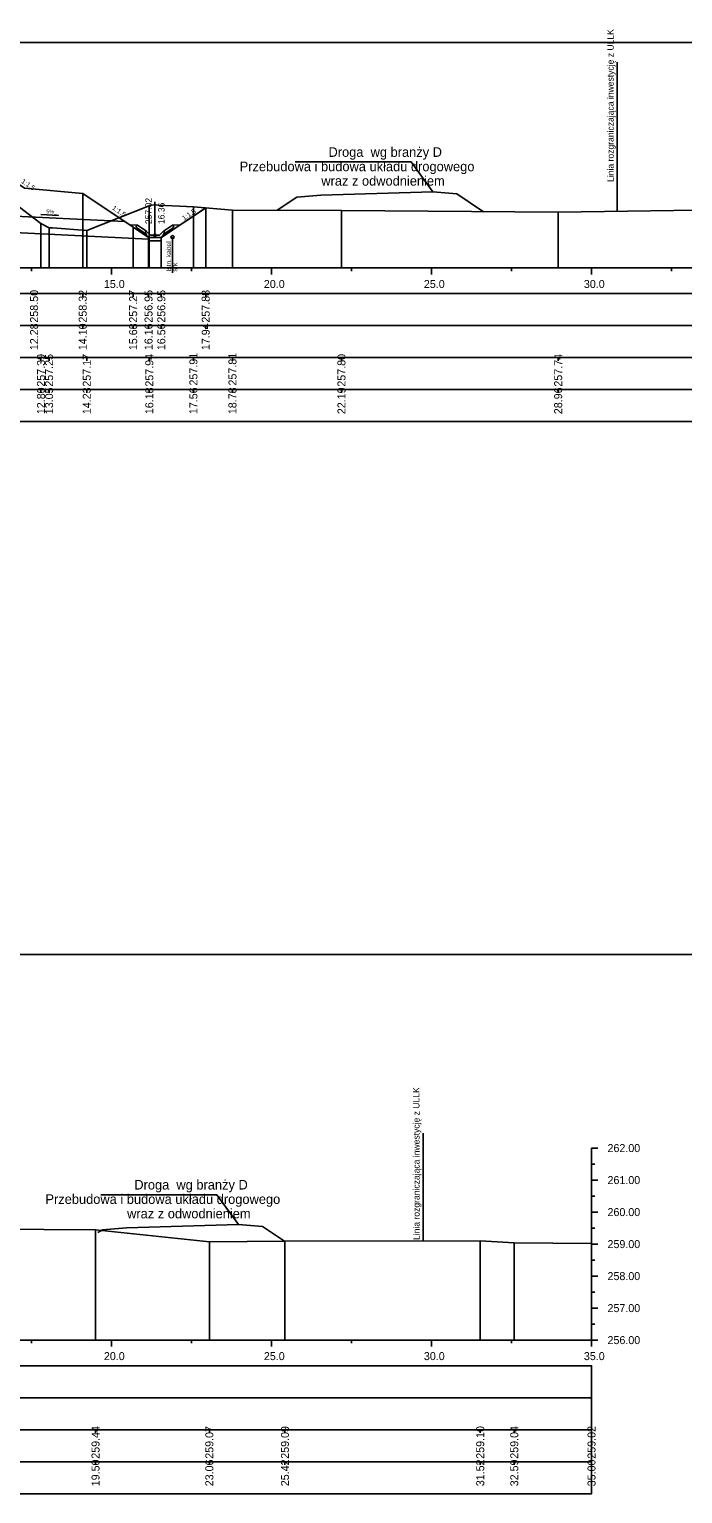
# Model space of a CAD drawing. Extents: x 6516023 to 6560129, y 5513077 to 5529206.
# Drawn here: x 6516497.89 to 6516518.31, y 5514501.31 to 5514547.06 of the extents above; entities that cross this region are included whole.
import ezdxf

# ---------------------------------------------------------------- set-up
doc = ezdxf.new("R2010")
doc.units = 0
for name, color, linetype in [('IR_default', 7, 'Continuous'), ('TOR_PRZEK_P-inne branze', 7, 'Continuous'), ('TOR_PRZEK_P-kable', 7, 'Continuous'), ('TOR_PRZEK_P-odwodnienie', 7, 'Continuous'), ('TOR_PRZEK_P-opisy', 7, 'Continuous'), ('TOR_PRZEK_P-schodkowanie+wymiana', 7, 'Continuous'), ('TOR_PRZEK_P-tabelka istniejace', 7, 'Continuous'), ('TOR_PRZEK_P-tabelka projektowane', 7, 'Continuous'), ('TOR_PRZEK_P-teren istniejacy', 7, 'Continuous'), ('TOR_PRZEK_P-uklad odniesienia', 7, 'Continuous'), ('TOR_PRZEK_P-warstwa ochronna II', 7, 'Continuous'), ('TOR_PS_T-granica PKP-projektowana', 7, 'Continuous'), ('TOR_PS_T-skarpy projektowane', 7, 'Continuous'), ('TOR_RAMKI-ramka+tabelka 1', 7, 'Continuous')]:
    doc.layers.add(name, color=color, linetype=linetype)

msp = doc.modelspace()

# ---------------------------------------------------------------- linework, layer by layer
at = {"layer": 'IR_default'}
msp.add_lwpolyline([(6516497.745, 5514542.101), (6516499.564, 5514541.929), (6516501.138, 5514540.88), (6516501.14, 5514540.878), (6516501.62, 5514540.559), (6516501.62, 5514540.558), (6516502.02, 5514540.558), (6516502.02, 5514540.558), (6516502.769, 5514541.057), (6516502.77, 5514541.058), (6516503.406, 5514541.483)], dxfattribs=at)
at = {"layer": 'TOR_PRZEK_P-inne branze'}
for p, q in [((6516509.824, 5514542.919), (6516506.2, 5514542.919)), ((6516510.5, 5514541.985), (6516509.824, 5514542.919)), ((6516503.755, 5514510.65), (6516500.131, 5514510.65)), ((6516504.431, 5514509.716), (6516503.755, 5514510.65))]:
    msp.add_line(p, q, dxfattribs=at)
for points in [[(6516505.636, 5514541.41), (6516506.25, 5514541.819), (6516507, 5514541.879), (6516508.75, 5514541.932), (6516510.5, 5514541.985), (6516511.25, 5514541.925), (6516512.09, 5514541.365)], [(6516500.04, 5514509.47), (6516500.181, 5514509.551), (6516500.931, 5514509.611), (6516502.681, 5514509.664), (6516504.431, 5514509.716), (6516505.181, 5514509.656), (6516505.873, 5514509.195)]]:
    msp.add_lwpolyline(points, dxfattribs=at)
at = {"layer": 'TOR_PRZEK_P-kable'}
msp.add_line((6516502.369, 5514540.568), (6516502.369, 5514539.458), dxfattribs=at)
msp.add_circle((6516502.369, 5514540.568), 0.05, dxfattribs=at)
at = {"layer": 'TOR_PRZEK_P-odwodnienie'}
for p, q in [((6516501.819, 5514540.628), (6516501.819, 5514541.672)), ((6516501.554, 5514540.754), (6516501.274, 5514540.941)), ((6516502.084, 5514540.754), (6516502.364, 5514540.941)), ((6516501.51, 5514540.687), (6516501.249, 5514540.861)), ((6516501.521, 5514540.704), (6516501.51, 5514540.687)), ((6516501.512, 5514540.723), (6516501.559, 5514540.747)), ((6516501.554, 5514540.754), (6516501.546, 5514540.741)), ((6516501.679, 5514540.628), (6516501.559, 5514540.747)), ((6516501.629, 5514540.558), (6516502.009, 5514540.558)), ((6516501.679, 5514540.628), (6516501.959, 5514540.628)), ((6516501.959, 5514540.628), (6516502.079, 5514540.747)), ((6516502.079, 5514540.747), (6516502.127, 5514540.723)), ((6516502.084, 5514540.754), (6516502.092, 5514540.741)), ((6516502.117, 5514540.704), (6516502.128, 5514540.687)), ((6516502.128, 5514540.687), (6516502.389, 5514540.861))]:
    msp.add_line(p, q, dxfattribs=at)
for points in [[(6516501.028, 5514540.952), (6516501.274, 5514540.941)], [(6516501.224, 5514540.914), (6516501.274, 5514540.941)], [(6516501.224, 5514540.914), (6516501.249, 5514540.861)], [(6516502.611, 5514540.952), (6516502.364, 5514540.941)], [(6516502.414, 5514540.914), (6516502.364, 5514540.941)], [(6516502.414, 5514540.914), (6516502.389, 5514540.861)], [(6516501.546, 5514540.741), (6516501.511, 5514540.723)], [(6516501.511, 5514540.723), (6516501.521, 5514540.704)], [(6516501.559, 5514540.628), (6516501.512, 5514540.723)], [(6516501.629, 5514540.558), (6516501.559, 5514540.628)], [(6516501.619, 5514540.558), (6516501.619, 5514540.559), (6516501.619, 5514540.558), (6516501.619, 5514540.558), (6516501.619, 5514540.558), (6516501.62, 5514540.558), (6516501.619, 5514540.558), (6516501.62, 5514540.559)], [(6516502.019, 5514540.558), (6516501.619, 5514540.558), (6516501.619, 5514540.458), (6516502.019, 5514540.458), (6516502.019, 5514540.558)], [(6516502.009, 5514540.558), (6516502.079, 5514540.628)], [(6516502.019, 5514540.558), (6516502.019, 5514540.559), (6516502.019, 5514540.558), (6516502.019, 5514540.558), (6516502.019, 5514540.558), (6516502.02, 5514540.558), (6516502.019, 5514540.558), (6516502.02, 5514540.559)], [(6516502.079, 5514540.628), (6516502.127, 5514540.723)], [(6516502.092, 5514540.741), (6516502.127, 5514540.723)], [(6516502.127, 5514540.723), (6516502.117, 5514540.704)]]:
    msp.add_lwpolyline(points, dxfattribs=at)
msp.add_circle((6516501.819, 5514540.628), 0.035, dxfattribs=at)
at = {"layer": 'TOR_PRZEK_P-schodkowanie+wymiana'}
for p, q in [((6516497.011, 5514541.248), (6516500.874, 5514541.055)), ((6516497.011, 5514540.733), (6516501.619, 5514540.503))]:
    msp.add_line(p, q, dxfattribs=at)
at = {"layer": 'TOR_PRZEK_P-tabelka istniejace'}
for p, q in [((6516498.259, 5514536.706), (6516498.259, 5514536.806)), ((6516498.511, 5514536.706), (6516498.511, 5514536.806)), ((6516499.689, 5514536.706), (6516499.689, 5514536.806)), ((6516501.644, 5514536.706), (6516501.644, 5514536.806)), ((6516503.022, 5514536.706), (6516503.022, 5514536.806)), ((6516504.243, 5514536.706), (6516504.243, 5514536.806)), ((6516507.649, 5514536.706), (6516507.649, 5514536.806)), ((6516514.421, 5514536.706), (6516514.421, 5514536.806)), ((6516446.663, 5514535.806), (6516520.463, 5514535.806)), ((6516498.259, 5514535.706), (6516498.259, 5514535.806)), ((6516498.511, 5514535.706), (6516498.511, 5514535.806)), ((6516499.689, 5514535.706), (6516499.689, 5514535.806)), ((6516501.644, 5514535.706), (6516501.644, 5514535.806)), ((6516503.022, 5514535.706), (6516503.022, 5514535.806)), ((6516504.243, 5514535.706), (6516504.243, 5514535.806)), ((6516507.649, 5514535.706), (6516507.649, 5514535.806)), ((6516514.421, 5514535.706), (6516514.421, 5514535.806)), ((6516499.963, 5514503.206), (6516499.963, 5514503.306)), ((6516503.52, 5514503.206), (6516503.52, 5514503.306)), ((6516505.884, 5514503.206), (6516505.884, 5514503.306)), ((6516511.985, 5514503.206), (6516511.985, 5514503.306)), ((6516513.049, 5514503.206), (6516513.049, 5514503.306)), ((6516515.463, 5514503.206), (6516515.463, 5514503.306)), ((6516441.663, 5514502.306), (6516515.463, 5514502.306)), ((6516499.963, 5514502.206), (6516499.963, 5514502.306)), ((6516503.52, 5514502.206), (6516503.52, 5514502.306)), ((6516505.884, 5514502.206), (6516505.884, 5514502.306)), ((6516511.985, 5514502.206), (6516511.985, 5514502.306)), ((6516513.049, 5514502.206), (6516513.049, 5514502.306)), ((6516515.463, 5514502.206), (6516515.463, 5514502.306))]:
    msp.add_line(p, q, dxfattribs=at)
for points in [[(6516501.644, 5514541.545), (6516501.644, 5514539.806), (6516501.644, 5514539.676), (6516501.644, 5514539.606)], [(6516503.022, 5514541.514), (6516503.022, 5514539.806), (6516503.022, 5514539.676), (6516503.022, 5514539.606)], [(6516504.243, 5514541.416), (6516504.243, 5514539.806), (6516504.243, 5514539.676), (6516504.243, 5514539.606)], [(6516507.649, 5514541.403), (6516507.649, 5514539.806), (6516507.649, 5514539.676), (6516507.649, 5514539.606)], [(6516514.421, 5514541.345), (6516514.421, 5514539.806), (6516514.421, 5514539.676), (6516514.421, 5514539.606)], [(6516498.259, 5514541), (6516498.259, 5514539.806), (6516498.259, 5514539.676), (6516498.259, 5514539.606)], [(6516498.511, 5514540.857), (6516498.511, 5514539.806), (6516498.511, 5514539.676), (6516498.511, 5514539.606)], [(6516499.689, 5514540.775), (6516499.689, 5514539.806), (6516499.689, 5514539.676), (6516499.689, 5514539.606)], [(6516499.963, 5514509.55), (6516499.963, 5514506.306), (6516499.963, 5514506.176), (6516499.963, 5514506.106)], [(6516503.52, 5514509.179), (6516503.52, 5514506.306), (6516503.52, 5514506.176), (6516503.52, 5514506.106)], [(6516505.884, 5514509.196), (6516505.884, 5514506.306), (6516505.884, 5514506.176), (6516505.884, 5514506.106)], [(6516511.985, 5514509.21), (6516511.985, 5514506.306), (6516511.985, 5514506.176), (6516511.985, 5514506.106)], [(6516513.049, 5514509.148), (6516513.049, 5514506.306), (6516513.049, 5514506.176), (6516513.049, 5514506.106)], [(6516515.463, 5514509.129), (6516515.463, 5514506.306), (6516515.463, 5514506.176), (6516515.463, 5514506.106)]]:
    msp.add_lwpolyline(points, dxfattribs=at)
for points in [[(6516446.663, 5514536.806), (6516446.663, 5514534.806), (6516520.463, 5514534.806), (6516520.463, 5514536.806)], [(6516441.663, 5514503.306), (6516441.663, 5514501.306), (6516515.463, 5514501.306), (6516515.463, 5514503.306)]]:
    msp.add_lwpolyline(points, close=True, dxfattribs=at)
at = {"layer": 'TOR_PRZEK_P-tabelka projektowane'}
for p, q in [((6516499.563, 5514538.706), (6516499.563, 5514538.806)), ((6516501.139, 5514538.706), (6516501.139, 5514538.806)), ((6516501.619, 5514538.706), (6516501.619, 5514538.806)), ((6516502.019, 5514538.706), (6516502.019, 5514538.806)), ((6516503.406, 5514538.706), (6516503.406, 5514538.806)), ((6516446.663, 5514537.806), (6516520.463, 5514537.806)), ((6516499.563, 5514537.706), (6516499.563, 5514537.806)), ((6516501.139, 5514537.706), (6516501.139, 5514537.806)), ((6516501.619, 5514537.706), (6516501.619, 5514537.806)), ((6516502.019, 5514537.706), (6516502.019, 5514537.806)), ((6516503.406, 5514537.706), (6516503.406, 5514537.806)), ((6516441.663, 5514504.306), (6516515.463, 5514504.306))]:
    msp.add_line(p, q, dxfattribs=at)
for points in [[(6516499.563, 5514541.929), (6516499.563, 5514539.806), (6516499.563, 5514539.676), (6516499.563, 5514539.606)], [(6516503.406, 5514541.483), (6516503.406, 5514539.806), (6516503.406, 5514539.676), (6516503.406, 5514539.606)], [(6516501.139, 5514540.878), (6516501.139, 5514539.806), (6516501.139, 5514539.676), (6516501.139, 5514539.606)], [(6516501.619, 5514540.558), (6516501.619, 5514539.806), (6516501.619, 5514539.676), (6516501.619, 5514539.606)], [(6516502.019, 5514540.558), (6516502.019, 5514539.806), (6516502.019, 5514539.676), (6516502.019, 5514539.606)]]:
    msp.add_lwpolyline(points, dxfattribs=at)
for points in [[(6516446.663, 5514538.806), (6516446.663, 5514536.806), (6516520.463, 5514536.806), (6516520.463, 5514538.806)], [(6516441.663, 5514505.306), (6516441.663, 5514503.306), (6516515.463, 5514503.306), (6516515.463, 5514505.306)]]:
    msp.add_lwpolyline(points, close=True, dxfattribs=at)
at = {"layer": 'TOR_PRZEK_P-teren istniejacy'}
for points in [[(6516496.56, 5514542.286), (6516498.259, 5514541), (6516498.511, 5514540.857), (6516498.618, 5514540.856), (6516499.689, 5514540.775), (6516501.644, 5514541.545), (6516501.706, 5514541.579), (6516503.022, 5514541.514), (6516504.243, 5514541.416), (6516507.649, 5514541.403), (6516514.421, 5514541.345), (6516520.207, 5514541.437)], [(6516470.294, 5514509.666), (6516472.392, 5514509.622), (6516473.693, 5514509.591), (6516473.799, 5514509.536), (6516474.234, 5514509.273), (6516474.323, 5514509.266), (6516474.772, 5514509.406), (6516474.98, 5514509.531), (6516475.508, 5514509.8), (6516485.107, 5514509.709), (6516486.668, 5514509.667), (6516487.104, 5514509.637), (6516487.29, 5514509.572), (6516487.492, 5514509.46), (6516488.223, 5514509.48), (6516490.732, 5514509.517), (6516494.042, 5514509.533), (6516496.723, 5514509.57), (6516499.963, 5514509.55), (6516503.52, 5514509.179), (6516505.884, 5514509.196), (6516511.985, 5514509.21), (6516513.049, 5514509.148), (6516515.463, 5514509.129)]]:
    msp.add_lwpolyline(points, dxfattribs=at)
at = {"layer": 'TOR_PRZEK_P-uklad odniesienia'}
for p, q in [((6516450.463, 5514539.606), (6516520.463, 5514539.606)), ((6516497.963, 5514539.506), (6516497.963, 5514539.606)), ((6516500.463, 5514539.406), (6516500.463, 5514539.606)), ((6516502.963, 5514539.506), (6516502.963, 5514539.606)), ((6516505.463, 5514539.406), (6516505.463, 5514539.606)), ((6516507.963, 5514539.506), (6516507.963, 5514539.606)), ((6516510.463, 5514539.406), (6516510.463, 5514539.606)), ((6516512.963, 5514539.506), (6516512.963, 5514539.606)), ((6516515.463, 5514539.406), (6516515.463, 5514539.606)), ((6516517.963, 5514539.506), (6516517.963, 5514539.606)), ((6516515.463, 5514512.106), (6516515.463, 5514506.106)), ((6516515.663, 5514512.106), (6516515.463, 5514512.106)), ((6516515.563, 5514511.606), (6516515.463, 5514511.606)), ((6516515.663, 5514511.106), (6516515.463, 5514511.106)), ((6516515.563, 5514510.606), (6516515.463, 5514510.606)), ((6516515.663, 5514510.106), (6516515.463, 5514510.106)), ((6516515.563, 5514509.606), (6516515.463, 5514509.606)), ((6516515.663, 5514509.106), (6516515.463, 5514509.106)), ((6516515.563, 5514508.606), (6516515.463, 5514508.606)), ((6516515.663, 5514508.106), (6516515.463, 5514508.106)), ((6516515.563, 5514507.606), (6516515.463, 5514507.606)), ((6516515.663, 5514507.106), (6516515.463, 5514507.106)), ((6516515.563, 5514506.606), (6516515.463, 5514506.606)), ((6516445.463, 5514506.106), (6516515.463, 5514506.106)), ((6516497.963, 5514506.006), (6516497.963, 5514506.106)), ((6516500.463, 5514505.906), (6516500.463, 5514506.106)), ((6516502.963, 5514506.006), (6516502.963, 5514506.106)), ((6516505.463, 5514505.906), (6516505.463, 5514506.106)), ((6516507.963, 5514506.006), (6516507.963, 5514506.106)), ((6516510.463, 5514505.906), (6516510.463, 5514506.106)), ((6516512.963, 5514506.006), (6516512.963, 5514506.106)), ((6516515.463, 5514505.906), (6516515.463, 5514506.106)), ((6516515.663, 5514506.106), (6516515.463, 5514506.106))]:
    msp.add_line(p, q, dxfattribs=at)
at = {"layer": 'TOR_PRZEK_P-warstwa ochronna II'}
msp.add_lwpolyline([(6516466.669, 5514541.495), (6516468.693, 5514540.184), (6516469.443, 5514540.184), (6516469.848, 5514540.454), (6516471.846, 5514541.786), (6516477.167, 5514542.099), (6516477.646, 5514542.418), (6516478.248, 5514542.442), (6516486.213, 5514542.761), (6516487.488, 5514542.812), (6516488.763, 5514542.762), (6516496.657, 5514542.445), (6516497.263, 5514542.421), (6516497.743, 5514542.102), (6516499.563, 5514541.929), (6516501.139, 5514540.878), (6516501.619, 5514540.558), (6516502.019, 5514540.558), (6516503.406, 5514541.483)], dxfattribs=at)
at = {"layer": 'TOR_PS_T-granica PKP-projektowana'}
for p, q in [((6516516.269, 5514541.374), (6516516.269, 5514546.032)), ((6516510.202, 5514509.205), (6516510.202, 5514512.574))]:
    msp.add_line(p, q, dxfattribs=at)
at = {"layer": 'TOR_PS_T-skarpy projektowane'}
msp.add_lwpolyline([(6516498.254, 5514541.274), (6516498.805, 5514541.244), (6516498.676, 5514541.268)], dxfattribs=at)
at = {"layer": 'TOR_RAMKI-ramka+tabelka 1'}
msp.add_lwpolyline([(6516362.013, 5514546.656), (6516609.513, 5514546.656), (6516609.513, 5514518.156), (6516362.013, 5514518.156)], close=True, dxfattribs=at)

# ---------------------------------------------------------------- texts
at = {"layer": 'TOR_PRZEK_P-inne branze'}
for s, p in [('Droga  wg branży D', (6516507.244, 5514543.079)), ('Przebudowa i budowa układu drogowego', (6516504.467, 5514542.629)), ('wraz z odwodnieniem ', (6516507.019, 5514542.179)), ('Droga  wg branży D', (6516501.175, 5514510.811)), ('Przebudowa i budowa układu drogowego', (6516498.398, 5514510.361)), ('wraz z odwodnieniem ', (6516500.95, 5514509.911))]:
    msp.add_text(s, height=0.3, dxfattribs=at).set_placement(p)
at = {"layer": 'TOR_PRZEK_P-kable'}
for s, height, p in [('Istn. kabel', 0.14999, (6516502.324, 5514539.494)), ('srk', 0.15, (6516502.518, 5514539.494))]:
    msp.add_text(s, height=height, rotation=90.0511, dxfattribs=at).set_placement(p)
at = {"layer": 'TOR_PRZEK_P-odwodnienie'}
for s, p in [('257.02', (6516501.719, 5514540.978)), ('16.36', (6516502.119, 5514540.978))]:
    msp.add_text(s, height=0.2, rotation=90, dxfattribs=at).set_placement(p)
at = {"layer": 'TOR_PRZEK_P-opisy'}
for rotation, p in [(325.9299, (6516497.628, 5514542.278)), (325.9299, (6516500.468, 5514541.449)), (34.0701, (6516502.733, 5514541.085))]:
    msp.add_text('1:1,5', height=0.15, rotation=rotation, dxfattribs=at).set_placement(p)
at = {"layer": 'TOR_PRZEK_P-tabelka istniejace'}
for s, p in [('257.39', (6516498.384, 5514535.898)), ('257.25', (6516498.636, 5514535.897)), ('257.17', (6516499.814, 5514535.898)), ('257.94', (6516501.769, 5514535.899)), ('257.91', (6516503.147, 5514535.933)), ('257.81', (6516504.368, 5514535.933)), ('257.80', (6516507.774, 5514535.898)), ('257.74', (6516514.546, 5514535.899)), ('12.80', (6516498.384, 5514535.038)), ('13.05', (6516498.636, 5514535.037)), ('14.23', (6516499.814, 5514535.038)), ('16.18', (6516501.769, 5514535.038)), ('17.56', (6516503.147, 5514535.038)), ('18.78', (6516504.368, 5514535.038)), ('22.19', (6516507.774, 5514535.038)), ('28.96', (6516514.546, 5514535.038)), ('259.44', (6516500.088, 5514502.399)), ('259.07', (6516503.645, 5514502.398)), ('259.09', (6516506.009, 5514502.398)), ('259.10', (6516512.11, 5514502.398)), ('259.04', (6516513.174, 5514502.399)), ('259.02', (6516515.588, 5514502.4)), ('19.50', (6516500.088, 5514501.538)), ('23.06', (6516503.645, 5514501.538)), ('25.42', (6516506.009, 5514501.54)), ('31.52', (6516512.11, 5514501.54)), ('32.59', (6516513.174, 5514501.538)), ('35.00', (6516515.588, 5514501.538))]:
    msp.add_text(s, height=0.25, rotation=90, dxfattribs=at).set_placement(p)
at = {"layer": 'TOR_PRZEK_P-tabelka projektowane'}
for s, p in [('258.50', (6516498.168, 5514537.898)), ('258.32', (6516499.688, 5514537.9)), ('257.27', (6516501.264, 5514537.898)), ('256.95', (6516501.744, 5514537.897)), ('256.95', (6516502.144, 5514537.897)), ('257.88', (6516503.531, 5514537.898)), ('12.28', (6516498.168, 5514537.038)), ('14.10', (6516499.688, 5514537.038)), ('15.68', (6516501.264, 5514537.038)), ('16.16', (6516501.744, 5514537.038)), ('16.56', (6516502.144, 5514537.038)), ('17.94', (6516503.531, 5514537.039))]:
    msp.add_text(s, height=0.25, rotation=90, dxfattribs=at).set_placement(p)
at = {"layer": 'TOR_PRZEK_P-uklad odniesienia'}
for s, p in [('15.0', (6516500.224, 5514538.981)), ('20.0', (6516505.224, 5514538.981)), ('25.0', (6516510.224, 5514538.981)), ('30.0', (6516515.224, 5514538.981)), ('262.00', (6516515.963, 5514511.981)), ('261.00', (6516515.963, 5514510.981)), ('260.00', (6516515.963, 5514509.981)), ('259.00', (6516515.963, 5514508.981)), ('258.00', (6516515.963, 5514507.981)), ('257.00', (6516515.963, 5514506.981)), ('256.00', (6516515.963, 5514505.981)), ('20.0', (6516500.224, 5514505.481)), ('25.0', (6516505.224, 5514505.481)), ('30.0', (6516510.224, 5514505.481)), ('35.0', (6516515.224, 5514505.481))]:
    msp.add_text(s, height=0.25, dxfattribs=at).set_placement(p)
at = {"layer": 'TOR_PS_T-granica PKP-projektowana'}
for p in [(6516516.158, 5514542.296), (6516510.091, 5514509.234)]:
    msp.add_text('Linia rozgraniczająca inwestycję z ULLK', height=0.2, rotation=90.0511, dxfattribs=at).set_placement(p)
at = {"layer": 'TOR_PS_T-skarpy projektowane'}
msp.add_text('5%', height=0.1159, dxfattribs=at).set_placement((6516498.428, 5514541.313))

doc.saveas('drawing.dxf')
